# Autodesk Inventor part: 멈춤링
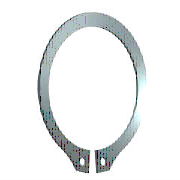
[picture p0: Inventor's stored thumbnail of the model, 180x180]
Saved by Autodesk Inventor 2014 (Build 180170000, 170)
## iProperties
IsCustomPart: 0
Created: 2009-02
Part Number: 멈춤링
Material: 강, 연강
Description: 리테이닝 링(C형)
Document SubType Name: Modeling
Standard: KS B 1336
Designer: KYOUNG IL JANG
Standards Organization: KS
Language: ko-KR
Size Designation: 22 x 1.2
Categories: <MemberInstance><Categories><Category DisplayName="샤프트 부품" InternalName="7f7aeb1f-a693-4053-b835-cee3144e0d98" Mnemonic="SHFT"><Category DisplayName="써클립" Inter
Density: 1 g/cm^3
Appearance: 강철
Author: KYOUNG IL JANG
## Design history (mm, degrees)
sketch "스케치1"
  geometry: L1 (-6, 0)-(6, 0) reference; L2 (0, 20.189)-(0, -80.536) reference; L3 (-48.09, 0)-(48.09, 0) reference; L4 (-0.5, -21.488)-(-0.5, -25.588); L5 (-0.5, -6.54)-(-0.5, -13.29); L6 (-2.795, 2.7)-(3.672, 2.7); L7 (0.5, -6.54)-(0.5, -13.29); L8 (0.5, -21.488)-(0.5, -25.588); C1 r 1 at (-2, -23.437); C2 r 1 at (2, -23.437); A1 r 10.5 centre (0, -11) between (0.5, -21.488) and (-0.5, -21.488); A2 r 13.025 centre (0, -10.325) between (5.149, -22.289) and (-5.149, -22.289); A3 r 14.597 centre (0, -11) between (-2.318, -25.411) and (-0.5, -25.588); A4 r 2 centre (-2, -23.437) between (-3.97, -23.781) and (-2.318, -25.411); A5 r 2 centre (-5.94, -24.126) between (-3.97, -23.781) and (-5.149, -22.289); A6 r 2 centre (5.94, -24.126) between (5.149, -22.289) and (3.97, -23.781); A7 r 2 centre (2, -23.437) between (2.318, -25.411) and (3.97, -23.781); A8 r 14.597 centre (0, -11) between (0.5, -25.588) and (2.318, -25.411)
  constraints: 16 point on circle, 12 end point, 10 centre point, 9 symmetric about line, 5 point on line, 4 tangent, 3 coincident, 2 horizontal, 1 perpendicular, 1 vertical, 5 other
  dimensions: "d0" = 21 diameter of A1 (= ND); "d1" = 4.1 distance of L4.end L4.start (= SRB2); "d6" = 0.5 distance between parallel lines of L2 L5 (= 0.25 x SD5); "d7" = 2.7 distance between parallel lines of L6 L3 (= SRB1); "d8" = 0.675 distance of A1.centre A2.centre (= 0.25 x SRB1); "d9" = 2 radius of A4 (= SD5); "d10" = 2 radius of A5 (= SD5); "d11" = 1.5 distance from line of L4 A4.centre (= 0.75 x SD5); "d12" = 2 diameter of C1 (= SD5); "d13" = 2 diameter of C2 (= SD5); "d14" = 11 distance from line of A1.centre L1 (= 0.5 x WD)
extrude "본체" new body sketch "스케치1" distance "d2" = 1.2 (= SD); taper "d3" = 0 deg
workaxis "Work Axis1"
workplane "Work Plane1"
body "Solid1"
other parameters: "WD" = 22 (= WDMIN) [user parameter; used in 1 equation term], "SD" = 1.2 [user parameter; used in 1 equation term], "SRB1" = 2.7 [user parameter; used in 2 equation terms], "ND" = 21 [user parameter; used in 1 equation term], "SRB2" = 4.1 [user parameter; used in 1 equation term], "SD5" = 2 [user parameter; used in 6 equation terms], "d15" = 0, "d16" = 0, "d17" = 0, "d41" = 0, "d42" = 0, "WDMIN" = 22 [user parameter; used in 1 equation term], "SD3" = 20.5 [user parameter], "WDMAX" = 24 [user parameter]
